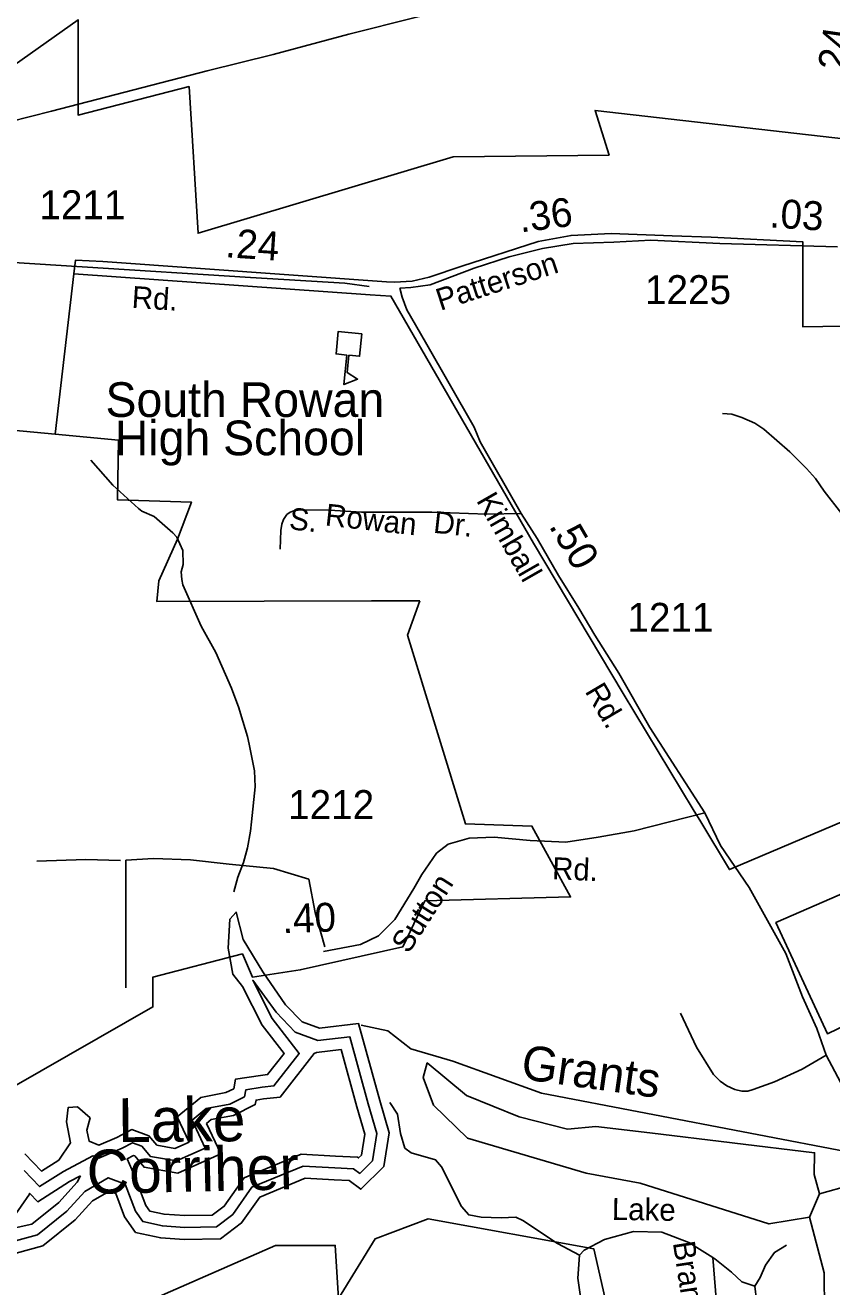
# Model space of a CAD drawing. Extents: x 1473865 to 1648260, y 639067 to 773536.
# Drawn here: x 1520113 to 1523597, y 663549 to 669004 of the extents above; entities that cross this region are included whole.
import ezdxf

# ---------------------------------------------------------------- set-up
doc = ezdxf.new("R2010")
doc.units = 0
for name, color, linetype in [('Exist Boundary Political City Limit New', 7, 'Continuous'), ('Exist Cultural Educational Facility High CELL', 7, 'Continuous'), ('Exist Cultural Educational Facility High Label', 7, 'Continuous'), ('Exist Hydrographic Buffer Line', 7, 'Continuous'), ('Exist Hydrographic Creek Single Shore', 7, 'Continuous'), ('Exist Hydrographic Creek Single Shore Label', 7, 'Continuous'), ('Exist Hydrographic Lake Shore', 7, 'Continuous'), ('Exist Hydrographic Lake Shore Label', 7, 'Continuous'), ('Exist Hydrographic Misc Water Feature', 7, 'Continuous'), ('Exist Hydrographic Pond Under 1500 Sq Ft', 7, 'Continuous'), ('Exist Road Non-System Type 51', 7, 'Continuous'), ('Exist Road Non-System Type 51 Label', 7, 'Continuous'), ('Exist Road Primary NC Attributed', 7, 'Continuous'), ('Exist Road Secondary Mileage Hundredths English Label', 7, 'Continuous'), ('Exist Road Secondary Type 51 Attributed', 7, 'Continuous'), ('Exist Road Secondary Type 51 Label', 7, 'Continuous'), ('Exist Road Secondary Type 51 Number Label', 7, 'Continuous'), ('Map Preparation Boundary City Limit Buffer Line', 7, 'Continuous')]:
    doc.layers.add(name, color=color, linetype=linetype)

msp = doc.modelspace()

# ---------------------------------------------------------------- linework, layer by layer
at = {"layer": 'Exist Boundary Political City Limit New'}
for p, q in [((1520322.6, 667929.8), (1520241.9, 667236.1)), ((1520241.9, 667236.1), (1520322.6, 667929.8))]:
    msp.add_line(p, q, dxfattribs=at)
for points in [[(1519994.8, 668782.1), (1520341.2, 669028.1), (1520341.2, 668615.5), (1520820.5, 668739), (1520859.1, 668105.1), (1521961.8, 668435.1), (1522635.5, 668442.8), (1522575, 668636.3), (1523660.9, 668511.8)], [(1526408.6, 667341.8), (1525724.6, 667376.4), (1525737, 666916.8), (1524430.8, 666944.2), (1524052.9, 666937.3), (1524090.2, 667467.2), (1523719.6, 667464.9), (1523729.8, 667704.2), (1523472.2, 667700.8), (1523473, 668067), (1523077.1, 668087.6), (1522908.6, 668094.2), (1522645, 668103), (1522471, 668095.4), (1522329, 668069.7), (1521999.5, 667962.2), (1521858.1, 667914.9), (1521783.9, 667898.2), (1521708.1, 667892.8), (1521673.5, 667894.1), (1520448.4, 667982.1), (1520329.4, 667987.9), (1520322.6, 667929.8)], [(1520322.6, 667929.8), (1521602.6, 667838.9), (1521692.6, 667832.9), (1522308.8, 666764.9)], [(1520241.9, 667236.1), (1519964.6, 667262.1)], [(1521817.1, 666515.9), (1521608.5, 666515.7), (1520680.9, 666512.6), (1520689.9, 666601.5), (1520770.6, 666782), (1520830.8, 666942.2), (1520511.1, 666952.2), (1520516.2, 667210.2), (1520241.9, 667236.1)], [(1522308.8, 666764.9), (1522696.8, 666115.2), (1522998.9, 665613.1), (1523031.4, 665559), (1523155.4, 665353), (1524188, 665791.3), (1524827.6, 665497.9), (1524812, 665117.6), (1524092, 665447.4), (1523631.1, 665243.4), (1523356.1, 665123.7), (1523578.5, 664643.3), (1523799, 664748.8), (1524320.4, 663878), (1524759.9, 663403.2), (1524926.9, 663232.1), (1525000, 663318.4), (1525164.1, 662906.1), (1525183.9, 662849.4), (1525277.4, 662607.6)], [(1518645.6, 663498.3), (1518631.4, 664257.7), (1519447.5, 664272), (1519461.9, 664515.6), (1520048.9, 664515.6), (1520063.2, 664415.3), (1520664.6, 664759.2), (1520664.6, 664888.1), (1521051.2, 664988.4), (1521094.2, 664888.1), (1521300.6, 664919.1), (1521744.5, 665019.4), (1521838.9, 665217.7), (1522469.2, 665235.1), (1522302.2, 665541.4), (1522014.8, 665550.6), (1521764.4, 666367.4), (1521817.1, 666515.9)], [(1522803.1, 662686.4), (1522569.1, 663713.2), (1521853.1, 663842.2), (1521624, 663756.2), (1521466.5, 663498.3), (1521452.2, 663727.6), (1521194.5, 663727.6), (1520507.1, 663426.7)]]:
    msp.add_lwpolyline(points, dxfattribs=at)
at = {"layer": 'Exist Cultural Educational Facility High CELL'}
msp.add_lwpolyline([(1521566.5, 667670.4), (1521557.1, 667573), (1521511.3, 667577.4), (1521504.1, 667502.6), (1521548.6, 667474), (1521489.4, 667450.4), (1521501.8, 667578.3), (1521455.9, 667582.7), (1521465.3, 667680.2)], close=True, dxfattribs=at)
at = {"layer": 'Exist Hydrographic Buffer Line'}
for points in [[(1520108.1, 664051.6), (1520174.4, 663982.1), (1520277.9, 664048), (1520405.3, 664115), (1520430.6, 664104.4), (1520530.7, 664148), (1520576.5, 664172.1), (1520616.3, 664157.6), (1520653.4, 664113), (1520765.9, 664093.4), (1520889.9, 664148.6), (1520833.5, 664269), (1520894.1, 664319.5), (1520996.5, 664338.7), (1521060.6, 664370.8), (1521065.6, 664400.6), (1521135.9, 664411.6), (1521187.1, 664417.3), (1521296.6, 664558.2), (1521179.9, 664708.5), (1521095.3, 664874.4), (1521197, 664735.8), (1521279.5, 664649.3), (1521377.3, 664613.7), (1521514.7, 664630.2), (1521594.5, 664340.3), (1521632, 664212), (1521612.9, 664094.2), (1521557.9, 664039.3), (1521530.6, 664059.4), (1521450.6, 664063.6), (1521313.3, 664071), (1521091.6, 663979.2), (1521009.7, 663861.6), (1520938.3, 663808.6), (1520801.1, 663805.7), (1520705.5, 663812), (1520620.6, 663830.6), (1520588.4, 663876.6), (1520543.7, 663993.2), (1520471.4, 664020.3), (1520369.9, 663960.9), (1520292.7, 663876.5), (1520165.1, 663773.7), (1519990.5, 663725.8)], [(1520582.9, 664032.7), (1520552.7, 664102.1), (1520580.3, 664116.7), (1520586, 664114.6), (1520626.3, 664066.1), (1520772.4, 664040.7), (1520957.9, 664123.2), (1520896.2, 664255), (1520916.5, 664271.9), (1521012.8, 664290), (1521106.5, 664336.9), (1521109.7, 664356), (1521142.6, 664361.2), (1521214.1, 664369.1), (1521361, 664558.2), (1521371.3, 664561.8), (1521477.3, 664574.6), (1521545.6, 664326.4), (1521580, 664208.8), (1521565.3, 664118.6), (1521552.8, 664106.1), (1521548.4, 664109.3), (1521453.3, 664114.3), (1521304.5, 664122.4), (1521058.4, 664020.4), (1520972.8, 663897.5), (1520921, 663859.1), (1520802.2, 663856.5), (1520712.6, 663862.5), (1520650.8, 663876), (1520633.6, 663900.7), (1520582.9, 664032.7)], [(1520351.8, 664029.4), (1520337.6, 664000.9), (1520257.8, 663913.7), (1520141.4, 663819.9), (1520023.2, 663793.3), (1520130.6, 663949.7), (1520131.6, 663953.3), (1520166.4, 663916.8), (1520303.4, 664004), (1520351.8, 664029.4)]]:
    msp.add_lwpolyline(points, dxfattribs=at)
at = {"layer": 'Exist Hydrographic Creek Single Shore'}
msp.add_lwpolyline([(1523695.2, 664127.1), (1522343, 664385.8), (1521960.9, 664524.8), (1521779, 664577.7), (1521680, 664655.2), (1521564, 664680.5)], dxfattribs=at)
at = {"layer": 'Exist Hydrographic Lake Shore'}
msp.add_lwpolyline([(1520111.3, 664123.6), (1520182.5, 664049), (1520257.1, 664096.5), (1520308, 664171.2), (1520291.1, 664262.9), (1520297.8, 664324), (1520338.6, 664327.4), (1520392.8, 664279.8), (1520379.3, 664225.5), (1520389.4, 664178), (1520430.1, 664161), (1520508.2, 664194.9), (1520572.6, 664228.9), (1520647.3, 664201.7), (1520681.2, 664161), (1520759.2, 664147.4), (1520820.3, 664174.6), (1520769.4, 664283.2), (1520871.1, 664368.1), (1520979.7, 664388.5), (1521013.6, 664405.4), (1521020.4, 664446.2), (1521129, 664463.2), (1521159.5, 664466.6), (1521230.7, 664558.2), (1521135.7, 664680.5), (1521050.9, 664846.8), (1521010.2, 664901.1), (1520989.9, 665013.2), (1520996.7, 665138.8), (1521023.8, 665169.4), (1521054.3, 665050.5), (1521139.1, 664911.3), (1521237.5, 664768.7), (1521308.8, 664694), (1521383.4, 664666.9), (1521553, 664687.2), (1521644.6, 664354.5), (1521685.3, 664215.3), (1521661.6, 664069.3), (1521563.2, 663970.9), (1521512.3, 664008.2), (1521447.8, 664011.6), (1521322.3, 664018.4), (1521125.6, 663936.9), (1521047.5, 663824.9), (1520956, 663757), (1520799.9, 663753.6), (1520698.1, 663760.4), (1520589.6, 663784.1), (1520542.1, 663852), (1520503.5, 663952.7), (1520476.3, 663962.9), (1520403, 663919.9), (1520328.4, 663838.5), (1520189.3, 663726.4), (1520016.3, 663678.9)], dxfattribs=at)
at = {"layer": 'Exist Hydrographic Misc Water Feature'}
for points in [[(1523640.9, 666892), (1523564.6, 666988.8), (1523527.2, 667043.7), (1523488, 667088), (1523417, 667159.2), (1523304.7, 667257.4), (1523265, 667283.7), (1523209.3, 667308.6), (1523165.5, 667321.8), (1523125.5, 667325.9)], [(1521014.2, 665256.2), (1521031.2, 665319.8), (1521056.2, 665383.3), (1521073.3, 665447.8), (1521086.4, 665519), (1521090.9, 665559.1), (1521105.5, 665711.4), (1521102.5, 665779.6), (1521080.3, 665895.8), (1521072.7, 665927.9), (1521042.3, 666028.6), (1521034.8, 666052.6), (1521004.1, 666136.9), (1520936.4, 666291.7), (1520872.2, 666405.5), (1520793, 666584.3), (1520789.4, 666608.2), (1520785.9, 666640.3), (1520794.3, 666672.1), (1520793.3, 666732.8), (1520768.3, 666790.8), (1520750.5, 666809.2), (1520669.5, 666880.6), (1520616, 666903), (1520602.1, 666914), (1520491.8, 667015.5), (1520395.4, 667123.3)], [(1523545, 663951.3), (1523679, 663988), (1523695.2, 664127.1)], [(1519534.9, 659751.8), (1519786.9, 659825.5), (1520078, 659819.6), (1520194.9, 659791), (1520740, 659491.1), (1520939, 659447.7), (1521089.9, 659461.1), (1521199, 659511.4), (1521715, 660009.8), (1521984.9, 660214.4), (1522214, 660485.5), (1522446.9, 660956.8), (1522489, 660988.8), (1522836, 661851.6), (1522999.9, 662173.3), (1523096, 662456.9), (1523299, 662626.8), (1523309, 662734.9), (1523436, 662883.4), (1523447, 663017.7), (1523567, 663281.2), (1523564, 663609.5), (1523501, 663850.4)]]:
    msp.add_lwpolyline(points, dxfattribs=at)
at = {"layer": 'Exist Hydrographic Pond Under 1500 Sq Ft'}
msp.add_line((1523501, 663850.4), (1523545, 663951.3), dxfattribs=at)
msp.add_lwpolyline([(1523501, 663850.4), (1523326, 663821.1), (1522770, 663996.4), (1522537, 664040.5), (1522023, 664192), (1521876.2, 664334.6), (1521831.4, 664454.3), (1521849.3, 664517.1), (1522019.7, 664376.5), (1522246.8, 664283.7), (1522456, 664229.9), (1522578.5, 664241.9), (1522811.7, 664214.9), (1523523, 664128.2), (1523521, 664033.8), (1523545, 663951.3)], dxfattribs=at)
at = {"layer": 'Exist Road Non-System Type 51'}
msp.add_line((1523264.9, 663551.5), (1523271.9, 663491.6), dxfattribs=at)
for points in [[(1521214.3, 666738.9), (1521217.7, 666818.8), (1521221.4, 666846.2), (1521228.7, 666866.6), (1521243.1, 666888.4), (1521257.3, 666898.1), (1521273.4, 666903.7), (1521301.3, 666908.2), (1521427.4, 666906.8), (1521565.3, 666898.3), (1521869.2, 666898.3), (1522107.2, 666889.7), (1522255.9, 666892.5)], [(1520162.3, 665389.2), (1520374.4, 665397.1), (1520524.4, 665392.3)], [(1520546.8, 665394.2), (1520666.6, 665401.4), (1520826.6, 665395.9), (1520994.3, 665376.7), (1521184.7, 665357.4), (1521338, 665311.3)], [(1520546.8, 664841.8), (1520546.8, 665394.2)], [(1521407.3, 665019.3), (1521365.6, 665167.1), (1521338, 665311.3)], [(1523572.9, 664551.2), (1523469, 664489.7), (1523350, 664435.8), (1523257.3, 664401.7), (1523234.2, 664395.4), (1523209.1, 664394.7), (1523178.9, 664402.7), (1523143.6, 664418), (1523114.6, 664438.8), (1523086.5, 664467), (1523012.9, 664584.5), (1522943.6, 664731.8)], [(1522507.7, 663686.3), (1522412.7, 663736), (1522262.4, 663834.9), (1522232.7, 663849.5), (1522168.8, 663846.8), (1522082.8, 663850.3), (1522029, 663859.4), (1521997.7, 663896), (1521910.9, 664067.7), (1521885.5, 664098.2), (1521780.1, 664128.2), (1521752.5, 664148.7), (1521733.7, 664211.1), (1521721.4, 664295.2), (1521688.2, 664345.9)], [(1522507.7, 663686.3), (1522527.9, 663707.9), (1522614.9, 663754.1), (1522741.4, 663787.6), (1522863.5, 663785.3), (1522980.6, 663741.1), (1523084, 663676.2), (1523092.9, 663669.1), (1523164.1, 663611.6), (1523209.3, 663570.7), (1523264.9, 663551.5)], [(1523264.9, 663551.5), (1523287.7, 663589.1), (1523310.8, 663642.6), (1523349.7, 663697.9), (1523402.4, 663729)], [(1522679.2, 662586.7), (1522652.5, 662691.4), (1522560.3, 663201.2), (1522528, 663395.7), (1522499.7, 663586.4), (1522507.7, 663686.3)], [(1523084, 663676.2), (1523101.8, 663442.9), (1523116.1, 663349.4), (1523150.3, 663262.8), (1523170.7, 663222.9), (1523227.8, 663126.1)]]:
    msp.add_lwpolyline(points, dxfattribs=at)
at = {"layer": 'Exist Road Primary NC Attributed'}
msp.add_lwpolyline([(1519132.1, 668347), (1519571.6, 668466.2), (1519862.3, 668540.8), (1520226.4, 668633.1), (1520898.8, 668807.5), (1521184.5, 668878.3), (1521510.6, 668965.5), (1521797.6, 669037.6), (1522023.8, 669090.7), (1522538.3, 669213.3), (1523205.7, 669365), (1523542, 669438.3), (1523670.9, 669464.8), (1523828.9, 669490.1)], dxfattribs=at)
at = {"layer": 'Exist Road Secondary Type 51 Attributed'}
for points in [[(1519132.1, 668347), (1519190.1, 668264.7), (1519261.9, 668167.9), (1519337.3, 668107.9), (1519403.5, 668059.2), (1519468.4, 668037.5), (1519542, 668021), (1519629.5, 668005.4), (1521085.7, 667913), (1521493.2, 667889.2), (1521599, 667875.1)], [(1523622, 668045.8), (1523113.4, 668060.7), (1522816.3, 668075), (1522656.2, 668066.1), (1522480.4, 668060), (1522348.1, 668038.4), (1522203.3, 668003.3), (1522052.4, 667954.4), (1521862, 667882.2), (1521778.6, 667870.9), (1521730.6, 667867.1)], [(1521730.6, 667867.1), (1521740.7, 667829.1), (1521760.9, 667773.5), (1521841.8, 667634.5), (1522052.9, 667266.6), (1522077.8, 667203.3), (1522255.9, 666892.5), (1522324, 666785.1), (1522416.8, 666625.4), (1522504.2, 666483.7), (1522573.8, 666366.3), (1522676.8, 666202.3), (1522812.1, 665967.7), (1523049.2, 665598.5)], [(1523049.2, 665598.5), (1522743.2, 665520.2), (1522587.6, 665493.1), (1522447.9, 665471.4), (1522294, 665478.3), (1522138.2, 665493.2), (1522030.3, 665489.4), (1521939.7, 665463), (1521888.9, 665424), (1521826.6, 665331.4), (1521792, 665270.9), (1521709.9, 665137.6), (1521639.6, 665067.2), (1521560.6, 665028.9), (1521401.3, 664998.1)], [(1523049.2, 665598.5), (1523116.3, 665457.9), (1523240, 665275.8), (1523399.3, 664990.7), (1523471.7, 664803), (1523533.2, 664665.9), (1523572.9, 664551.2), (1523648, 664409.6), (1523744.3, 664222.8), (1523785, 664146.3)]]:
    msp.add_lwpolyline(points, dxfattribs=at)
at = {"layer": 'Map Preparation Boundary City Limit Buffer Line'}
for p, q in [((1520322.6, 667929.8), (1520241.9, 667236.1)), ((1520241.9, 667236.1), (1520322.6, 667929.8))]:
    msp.add_line(p, q, dxfattribs=at)
for points in [[(1519994.8, 668782.1), (1520341.2, 669028.1), (1520341.2, 668615.5), (1520820.5, 668739), (1520859.1, 668105.1), (1521961.8, 668435.1), (1522635.5, 668442.8), (1522575, 668636.3), (1523660.9, 668511.8)], [(1526408.6, 667341.8), (1525724.6, 667376.4), (1525737, 666916.8), (1524430.8, 666944.2), (1524052.9, 666937.3), (1524090.2, 667467.2), (1523719.6, 667464.9), (1523729.8, 667704.2), (1523472.2, 667700.8), (1523473, 668067), (1523077.1, 668087.6), (1522908.6, 668094.2), (1522645, 668103), (1522471, 668095.4), (1522329, 668069.7), (1521999.5, 667962.2), (1521858.1, 667914.9), (1521783.9, 667898.2), (1521708.1, 667892.8), (1521673.5, 667894.1), (1520448.4, 667982.1), (1520329.4, 667987.9), (1520322.6, 667929.8)], [(1520322.6, 667929.8), (1521602.6, 667838.9), (1521692.6, 667832.9), (1522308.8, 666764.9)], [(1520241.9, 667236.1), (1519964.6, 667262.1)], [(1521817.1, 666515.9), (1521608.5, 666515.7), (1520680.9, 666512.6), (1520689.9, 666601.5), (1520770.6, 666782), (1520830.8, 666942.2), (1520511.1, 666952.2), (1520516.2, 667210.2), (1520241.9, 667236.1)], [(1522308.8, 666764.9), (1522696.8, 666115.2), (1522998.9, 665613.1), (1523031.4, 665559), (1523155.4, 665353), (1524188, 665791.3), (1524827.6, 665497.9), (1524812, 665117.6), (1524092, 665447.4), (1523631.1, 665243.4), (1523356.1, 665123.7), (1523578.5, 664643.3), (1523799, 664748.8), (1524320.4, 663878), (1524759.9, 663403.2), (1524926.9, 663232.1), (1525000, 663318.4), (1525164.1, 662906.1), (1525183.9, 662849.4), (1525277.4, 662607.6)], [(1518645.6, 663498.3), (1518631.4, 664257.7), (1519447.5, 664272), (1519461.9, 664515.6), (1520048.9, 664515.6), (1520063.2, 664415.3), (1520664.6, 664759.2), (1520664.6, 664888.1), (1521051.2, 664988.4), (1521094.2, 664888.1), (1521300.6, 664919.1), (1521744.5, 665019.4), (1521838.9, 665217.7), (1522469.2, 665235.1), (1522302.2, 665541.4), (1522014.8, 665550.6), (1521764.4, 666367.4), (1521817.1, 666515.9)], [(1522803.1, 662686.4), (1522569.1, 663713.2), (1521853.1, 663842.2), (1521624, 663756.2), (1521466.5, 663498.3), (1521452.2, 663727.6), (1521194.5, 663727.6), (1520507.1, 663426.7)]]:
    msp.add_lwpolyline(points, dxfattribs=at)

# ---------------------------------------------------------------- texts
at = {"layer": 'Exist Cultural Educational Facility High Label'}
for s, p in [('South Rowan', (1520459.4, 667310.4)), ('High School', (1520499.4, 667144.8))]:
    msp.add_text(s, height=150, rotation=0, dxfattribs=at).set_placement(p)
at = {"layer": 'Exist Hydrographic Creek Single Shore Label'}
msp.add_text('Grants', height=150, rotation=352.0133, dxfattribs=at).set_placement((1522249.9, 664448.6))
at = {"layer": 'Exist Hydrographic Lake Shore Label'}
for s, rotation, p in [('Lake', 0.459, (1520514, 664174.3)), ('Corriher', 1.3236, (1520380, 663950))]:
    msp.add_text(s, height=190, rotation=rotation, dxfattribs=at).set_placement(p)
at = {"layer": 'Exist Road Non-System Type 51 Label'}
for s, rotation, p in [('S.', 353.6827, (1521249.8, 666825.1)), ('Rowan', 353.6827, (1521405.3, 666841.6)), ('Dr.', 353.6827, (1521873, 666810)), ('Lake', 358.9386, (1522646.7, 663838.6)), ('Branchview', 278.6779, (1522910.7, 663739.6))]:
    msp.add_text(s, height=95, rotation=rotation, dxfattribs=at).set_placement(p)
at = {"layer": 'Exist Road Secondary Mileage Hundredths English Label'}
for s, rotation, p in [('.24', 81.8523, (1523653.9, 668756.5)), ('.36', 7.2475, (1522252.6, 668108)), ('.03', 356.4035, (1523326.5, 668130.3)), ('.24', 356.1871, (1520974.8, 668001.4)), ('.50', 300.1569, (1522373.2, 666839)), ('.40', 2.03, (1521225, 665077.7))]:
    msp.add_text(s, height=125, rotation=rotation, dxfattribs=at).set_placement(p)
at = {"layer": 'Exist Road Secondary Type 51 Label'}
for s, rotation, p in [('Patterson', 17.9882, (1521906.2, 667769)), ('Rd.', 356.3691, (1520570.8, 667782.2)), ('Kimball', 299.8122, (1522059.5, 666949.4)), ('Rd.', 300.5989, (1522528.6, 666124.1)), ('Rd.', 357.4312, (1522387.7, 665312.1)), ('Sutton', 57.2905, (1521768.6, 664985.4))]:
    msp.add_text(s, height=95, rotation=rotation, dxfattribs=at).set_placement(p)
at = {"layer": 'Exist Road Secondary Type 51 Number Label'}
for s, p in [('1211', (1520173.7, 668165.6)), ('1225', (1522790.5, 667798.5)), ('1211', (1522714.8, 666381.4)), ('1212', (1521248.5, 665571.7))]:
    msp.add_text(s, height=125, dxfattribs=at).set_placement(p)

doc.saveas('drawing.dxf')
